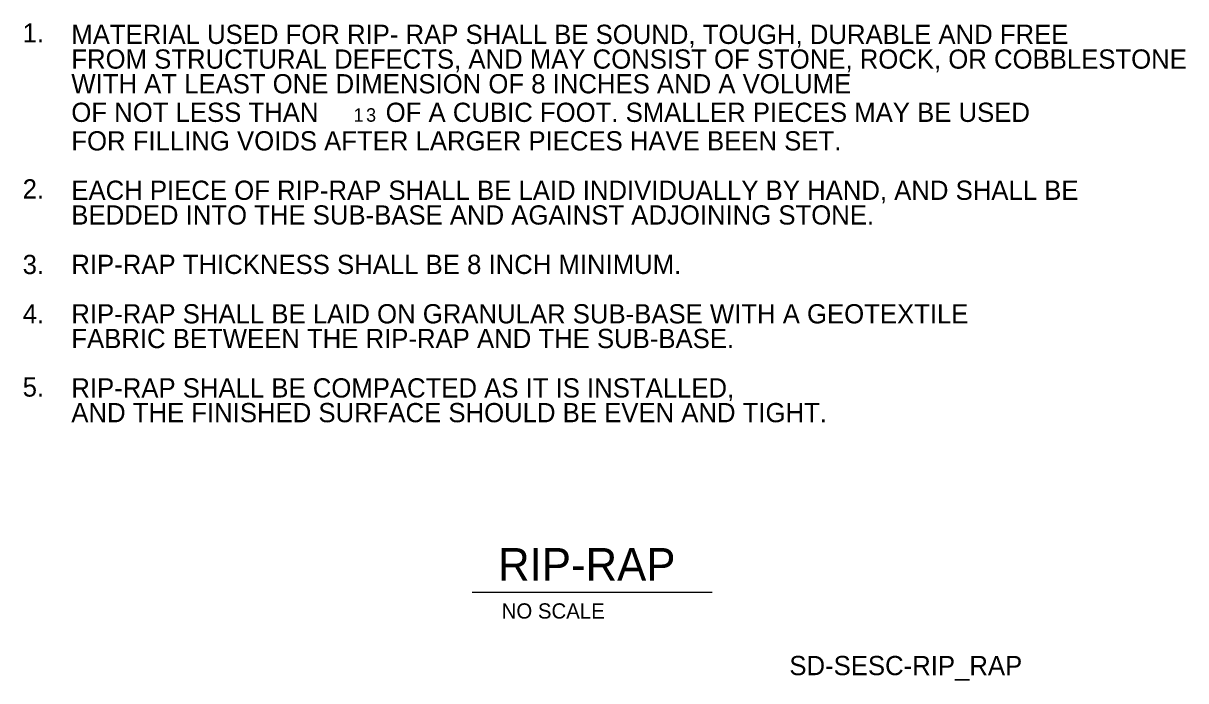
# Model space of a CAD drawing. Extents: x 10048.1 to 10113.8, y 9930.9 to 10007.5.
# Drawn here: x 10048.1 to 10111.3, y 9930.9 to 9966.6 of the extents above; entities that cross this region are included whole.
import ezdxf

# ---------------------------------------------------------------- set-up
doc = ezdxf.new("R2010")
doc.units = 0
doc.layers.add('G-ANNO-TEXT', color=7, linetype='Continuous')

msp = doc.modelspace()

# ---------------------------------------------------------------- linework, layer by layer
at = {"layer": 'G-ANNO-TEXT'}
msp.add_line((10072.523, 9935.743), (10085.56, 9935.743), dxfattribs=at)

# ---------------------------------------------------------------- texts
for s, height, p in [('1.', 1.044, (10048.108, 9965.577)), ('MATERIAL USED FOR RIP- RAP SHALL BE SOUND, TOUGH, DURABLE AND FREE', 1.044, (10050.751, 9965.498)), ('FROM STRUCTURAL DEFECTS, AND MAY CONSIST OF STONE, ROCK, OR COBBLESTONE', 1.044, (10050.751, 9964.157)), ('WITH AT LEAST ONE DIMENSION OF 8 INCHES AND A VOLUME', 1.044, (10050.751, 9962.816)), ('OF NOT LESS THAN ', 1.044, (10050.751, 9961.266)), (' OF A CUBIC FOOT. SMALLER PIECES MAY BE USED', 1.044, (10067.435, 9961.266)), ('1', 0.731, (10066.078, 9961.277)), ('3', 0.731, (10066.757, 9961.277)), ('FOR FILLING VOIDS AFTER LARGER PIECES HAVE BEEN SET.', 1.044, (10050.751, 9959.717)), ('2.', 1.044, (10048.108, 9957.109)), ('EACH PIECE OF RIP-RAP SHALL BE LAID INDIVIDUALLY BY HAND, AND SHALL BE', 1.044, (10050.751, 9957.035)), ('BEDDED INTO THE SUB-BASE AND AGAINST ADJOINING STONE.', 1.044, (10050.751, 9955.694)), ('3.', 1.044, (10048.108, 9953.007)), ('RIP-RAP THICKNESS SHALL BE 8 INCH MINIMUM.', 1.044, (10050.751, 9953.012)), ('4.', 1.044, (10048.108, 9950.328)), ('RIP-RAP SHALL BE LAID ON GRANULAR SUB-BASE WITH A GEOTEXTILE', 1.044, (10050.751, 9950.33)), ('FABRIC BETWEEN THE RIP-RAP AND THE SUB-BASE.', 1.044, (10050.751, 9948.989)), ('5.', 1.044, (10048.108, 9946.356)), ('RIP-RAP SHALL BE COMPACTED AS IT IS INSTALLED,', 1.044, (10050.751, 9946.307)), ('AND THE FINISHED SURFACE SHOULD BE EVEN AND TIGHT.', 1.044, (10050.751, 9944.966)), ('RIP-RAP', 1.776, (10073.926, 9936.362)), ('NO SCALE', 0.828, (10074.12, 9934.309)), ('SD-SESC-RIP_RAP', 1.044, (10089.744, 9931.238))]:
    msp.add_text(s, height=height, dxfattribs=at).set_placement(p)

doc.saveas('drawing.dxf')
